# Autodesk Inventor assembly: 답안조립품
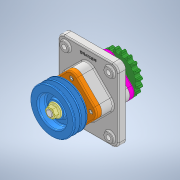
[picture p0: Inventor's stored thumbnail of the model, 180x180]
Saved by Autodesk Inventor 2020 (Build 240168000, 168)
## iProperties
Created: 2021-07
Part Number: 답안조립품
Document SubType Name: Assembly
Designer: Owner
Author: Owner
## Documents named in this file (16)
- C:\Users\Owner\Desktop\710707V1005\답안조립품.iam
- C:\Users\Owner\Desktop\710707V1005\답안부품.ipt
- C:\Users\Owner\Desktop\710707V1005\M16 너트.ipt
- C:\Users\Owner\Desktop\710707V1005\V-벨트풀리.ipt
- C:\Users\Owner\Desktop\710707V1005\멈춤나사 M4.ipt
- C:\Users\Owner\Desktop\710707V1005\베어링 6206.ipt
- C:\Users\Owner\Desktop\710707V1005\볼트 M6.ipt
- C:\Users\Owner\Desktop\710707V1005\부시.ipt
- C:\Users\Owner\Desktop\710707V1005\오일실 30x42x8.ipt
- C:\Users\Owner\Desktop\710707V1005\오일실 30x45x8.ipt
- C:\Users\Owner\Desktop\710707V1005\체인 스프로킷.ipt
- C:\Users\Owner\Desktop\710707V1005\축.ipt
- C:\Users\Owner\Desktop\710707V1005\커버A.ipt
- C:\Users\Owner\Desktop\710707V1005\커버B.ipt
- C:\Users\Owner\Desktop\710707V1005\키 6x6x18.ipt
- C:\Users\Owner\Desktop\710707V1005\키 6x6x20.ipt
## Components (3 placed, 2 different names)
1. M16 너트:1 — 각도:2, 각도:4, 각도:5
2. V-벨트풀리:1 — 각도:3
3. M16 너트:2 — 각도:4, 각도:5
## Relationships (4: Angle 4)
- 각도:2 [Angle]: M16 너트:1
- 각도:3 [Angle]: V-벨트풀리:1
- 각도:4 [Angle]: M16 너트:1 ↔ M16 너트:2
- 각도:5 [Angle]: M16 너트:1 ↔ M16 너트:2
